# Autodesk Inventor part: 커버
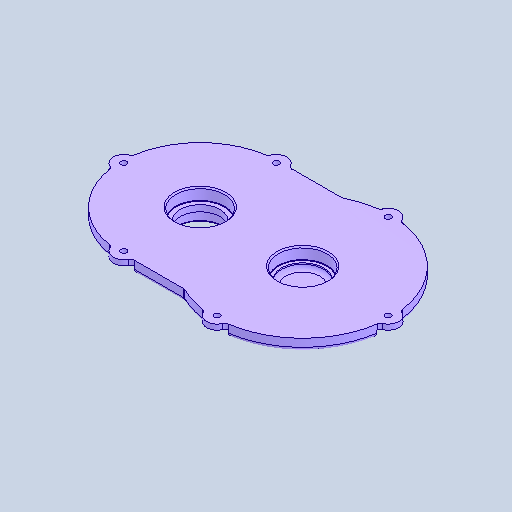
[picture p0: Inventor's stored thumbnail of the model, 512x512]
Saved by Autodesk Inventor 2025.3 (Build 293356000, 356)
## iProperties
Created: 2025-09
Part Number: 커버
Material: 알루미늄 6061
Document SubType Name: Modeling
Designer: PC-15
Density: 2.7 g/cm^3
Appearance: 기본값
Author: jhkim
Sending System: Autodesk Inventor 2026
Preprocessor: ST-DEVELOPER v20.1
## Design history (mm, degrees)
feature "솔리드1"
node "솔리드2"
